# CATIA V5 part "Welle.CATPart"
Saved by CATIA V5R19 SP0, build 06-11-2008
Part number: welle
Bounding box of the stored display mesh (mm): x -15 to 15, y -30 to 100, z -10 to 20.122
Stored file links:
  H:\Bachelorarbeit_Hahn\Neue Vereinfachung\Welle.CATPart
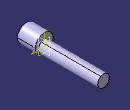
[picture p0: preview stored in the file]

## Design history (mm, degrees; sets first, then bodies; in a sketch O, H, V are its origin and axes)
Body1 (main body)
  Sketch1 on yz-plane, origin (0, 0, 0), H (0, 1, 0), V (0, 0, 1)
    line L1 (0, 0) -> (100, 0)
    line L2 (100, 0) -> (100, 10)
    line L3 (100, 10) -> (0, 10)
    line L4 (0, 10) -> (0, 0)
    distance L3 L1 = 10
    distance L2 L4 = 100
    horizontal: L1 H, L3 H
    vertical: L2 V, L4 V
  Shaft1: profile Sketch1, axis Sketch1.L1, angle 360
  Sketch2 on zx-plane, origin (0, 0, 0), H (-1, 0, 0), V (0, 0, 1)
    circle A1 centre (0, 5.1217) radius 15
    point P1 (0, 5.1217)
    radius A1 = 15
    coincidence: P1 V
  Sketch3 on face of Shaft1 from Sketch1.L4, origin (0, 0, 0), H (1, 0, 0), V (0, 0, 1)
    reference projected circle E1 centre (0, 0) radius 10 from edge [face of Shaft1 from Sketch1.L4 | face of Shaft1 from Sketch1.L3]
    radius E1 = 10 (reference)
  Pad1: profile Sketch2, direction (0, -1, 0), length 30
